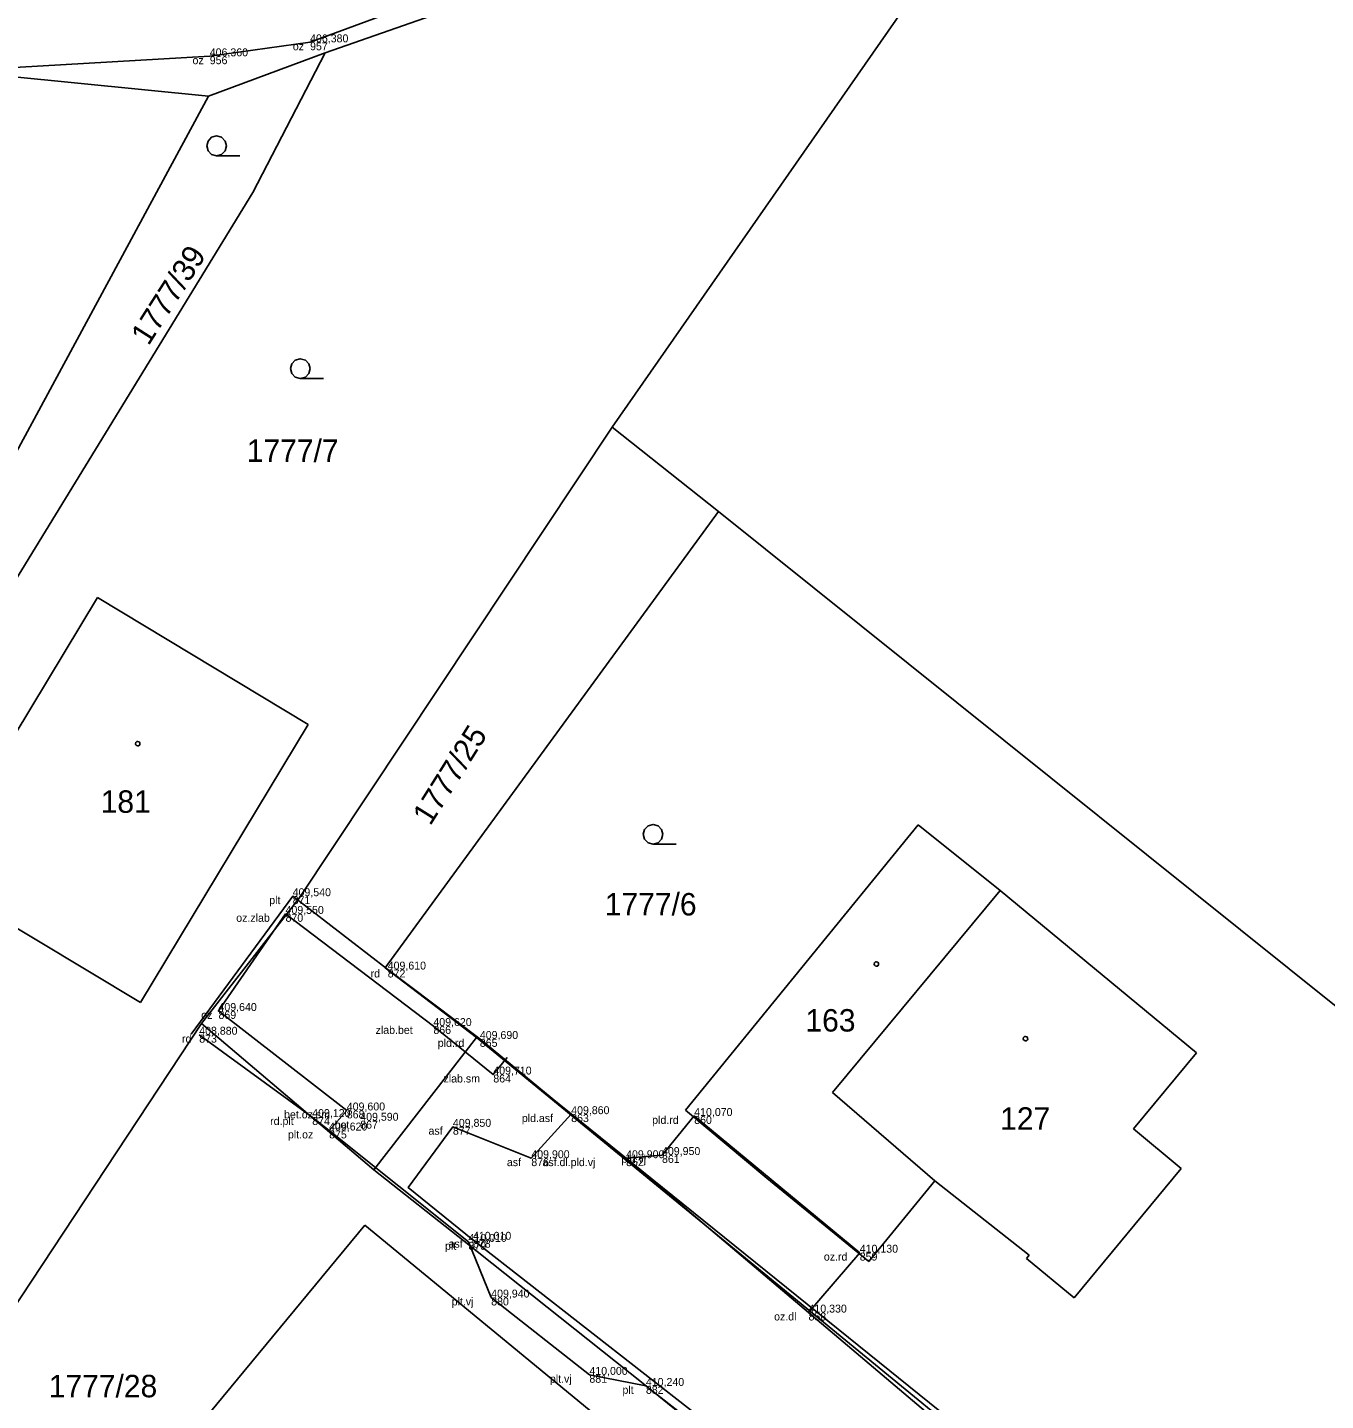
# Model space of a CAD drawing. Extents: x -747792 to -745414, y -1093712 to -1091463.
# Drawn here: x -746956.8 to -746907.6, y -1092211.1 to -1092159 of the extents above; entities that cross this region are included whole.
import ezdxf

# ---------------------------------------------------------------- set-up
doc = ezdxf.new("R2010")
doc.units = 0
for name, color, linetype in [('Budovy', 7, 'Continuous'), ('Hladina', 7, 'Continuous'), ('Koleje_dopravní prvky', 7, 'Continuous'), ('Nezařazené objekty', 7, 'Continuous'), ('Nivelační značky_hrany', 7, 'Continuous'), ('Ploty_opěrné zdi', 7, 'Continuous'), ('Popisy objektů_povrchů', 7, 'Continuous'), ('Pracovní_bod PPBP - výška', 7, 'Continuous'), ('Rozhraní ploch', 7, 'Continuous'), ('Stromy_porost', 7, 'Continuous'), ('Výškopis', 7, 'Continuous')]:
    doc.layers.add(name, color=color, linetype=linetype)

msp = doc.modelspace()

# ---------------------------------------------------------------- linework, layer by layer
at = {"layer": 'Budovy'}
for points in [[(-746949.6, -1092163.9), (-746949.79, -1092163.85), (-746949.925, -1092163.71), (-746949.975, -1092163.525), (-746949.925, -1092163.34), (-746949.79, -1092163.2), (-746949.6, -1092163.15), (-746949.41, -1092163.2), (-746949.275, -1092163.34), (-746949.225, -1092163.525), (-746949.275, -1092163.71), (-746949.41, -1092163.85), (-746949.6, -1092163.9), (-746948.725, -1092163.9)], [(-746946.43, -1092172.34), (-746946.62, -1092172.29), (-746946.755, -1092172.15), (-746946.805, -1092171.965), (-746946.755, -1092171.78), (-746946.62, -1092171.64), (-746946.43, -1092171.59), (-746946.24, -1092171.64), (-746946.105, -1092171.78), (-746946.055, -1092171.965), (-746946.105, -1092172.15), (-746946.24, -1092172.29), (-746946.43, -1092172.34), (-746945.555, -1092172.34)], [(-746933.07, -1092189.99), (-746933.26, -1092189.94), (-746933.395, -1092189.8), (-746933.445, -1092189.615), (-746933.395, -1092189.43), (-746933.26, -1092189.29), (-746933.07, -1092189.24), (-746932.88, -1092189.29), (-746932.745, -1092189.43), (-746932.695, -1092189.615), (-746932.745, -1092189.8), (-746932.88, -1092189.94), (-746933.07, -1092189.99), (-746932.195, -1092189.99)]]:
    msp.add_lwpolyline(points, dxfattribs=at)
at = {"layer": 'Hladina'}
for p, q in [((-746946.06, -1092159.6), (-746946.06, -1092159.6)), ((-746949.86, -1092160.13), (-746949.86, -1092160.13)), ((-746946.72, -1092191.96), (-746946.72, -1092191.96)), ((-746946.99, -1092192.63), (-746946.99, -1092192.63)), ((-746943.12, -1092194.74), (-746943.12, -1092194.74)), ((-746949.53, -1092196.31), (-746949.53, -1092196.31)), ((-746941.39, -1092196.88), (-746941.39, -1092196.88)), ((-746950.26, -1092197.21), (-746950.26, -1092197.21)), ((-746939.63, -1092197.37), (-746939.63, -1092197.37)), ((-746939.12, -1092198.72), (-746939.12, -1092198.72)), ((-746944.67, -1092200.08), (-746944.67, -1092200.08)), ((-746936.17, -1092200.22), (-746936.17, -1092200.22)), ((-746945.98, -1092200.33), (-746945.98, -1092200.33)), ((-746944.16, -1092200.47), (-746944.16, -1092200.47)), ((-746940.65, -1092200.7), (-746940.65, -1092200.7)), ((-746931.51, -1092200.29), (-746931.51, -1092200.29)), ((-746945.34, -1092200.84), (-746945.34, -1092200.84)), ((-746932.73, -1092201.77), (-746932.73, -1092201.77)), ((-746937.68, -1092201.89), (-746937.68, -1092201.89)), ((-746934.09, -1092201.89), (-746934.09, -1092201.89)), ((-746940.06, -1092205.06), (-746940.06, -1092205.06)), ((-746939.89, -1092204.98), (-746939.89, -1092204.98)), ((-746925.24, -1092205.47), (-746925.24, -1092205.47)), ((-746939.2, -1092207.17), (-746939.2, -1092207.17)), ((-746927.18, -1092207.74), (-746927.18, -1092207.74)), ((-746935.48, -1092210.1), (-746935.48, -1092210.1)), ((-746933.34, -1092210.52), (-746933.34, -1092210.52))]:
    msp.add_line(p, q, dxfattribs=at)
at = {"layer": 'Nezařazené objekty'}
for points in [[(-746898.2, -1092136.84), (-746901.82, -1092139.52), (-746907.92, -1092143.31), (-746914.89, -1092147.23), (-746921.83, -1092150.74), (-746928.99, -1092153.69), (-746935.25, -1092155.97), (-746941.16, -1092157.77), (-746946.06, -1092159.6), (-746949.86, -1092160.13)], [(-746949.86, -1092160.13), (-746970.11, -1092161.3), (-746974.56, -1092162.83), (-746976.66, -1092164.29), (-746978.34, -1092165.95)], [(-746950.56, -1092197.19), (-746946.72, -1092191.96), (-746943.12, -1092194.74)], [(-746945.34, -1092200.84), (-746944.67, -1092200.08), (-746949.53, -1092196.31), (-746946.99, -1092192.63)], [(-746939.63, -1092197.37), (-746936.17, -1092200.22)], [(-746936.17, -1092200.22), (-746934.09, -1092201.89)], [(-746945.34, -1092200.84), (-746945.98, -1092200.33)], [(-746932.73, -1092201.77), (-746931.51, -1092200.29)], [(-746939.2, -1092207.17), (-746940.06, -1092205.06), (-746945.34, -1092200.84)], [(-746925.24, -1092205.47), (-746927.18, -1092207.74), (-746922.75, -1092211.49)], [(-746930.18, -1092221.49), (-746926.79, -1092217.36), (-746927.43, -1092215.14), (-746933.34, -1092210.52), (-746935.48, -1092210.1)]]:
    msp.add_lwpolyline(points, dxfattribs=at)
at = {"layer": 'Nivelační značky_hrany'}
for points in [[(-746946.99, -1092192.63), (-746941.39, -1092196.88), (-746939.12, -1092198.72), (-746938.59, -1092198.07)], [(-746954.31, -1092247.58), (-746952.61, -1092247.87), (-746950.91, -1092247.12), (-746949.5, -1092246), (-746932.35, -1092225.35), (-746926.2, -1092217.84), (-746927.09, -1092214.99), (-746939.89, -1092204.98), (-746942.35, -1092203), (-746940.65, -1092200.7), (-746937.68, -1092201.89), (-746936.17, -1092200.22)], [(-746934.09, -1092201.89), (-746927.18, -1092207.74)]]:
    msp.add_lwpolyline(points, dxfattribs=at)
at = {"layer": 'Ploty_opěrné zdi'}
for points in [[(-746952.59, -1092186.095), (-746952.54, -1092186.105), (-746952.515, -1092186.15), (-746952.505, -1092186.18), (-746952.515, -1092186.225), (-746952.555, -1092186.26), (-746952.59, -1092186.265), (-746952.635, -1092186.25), (-746952.665, -1092186.22), (-746952.675, -1092186.18), (-746952.665, -1092186.135), (-746952.625, -1092186.1)], [(-746924.61, -1092194.445), (-746924.56, -1092194.455), (-746924.535, -1092194.5), (-746924.525, -1092194.53), (-746924.535, -1092194.575), (-746924.575, -1092194.61), (-746924.61, -1092194.615), (-746924.655, -1092194.6), (-746924.685, -1092194.57), (-746924.695, -1092194.53), (-746924.685, -1092194.485), (-746924.645, -1092194.45)], [(-746918.96, -1092197.275), (-746918.91, -1092197.285), (-746918.885, -1092197.33), (-746918.875, -1092197.36), (-746918.885, -1092197.405), (-746918.925, -1092197.44), (-746918.96, -1092197.445), (-746919.005, -1092197.43), (-746919.035, -1092197.4), (-746919.045, -1092197.36), (-746919.035, -1092197.315), (-746918.995, -1092197.28)]]:
    msp.add_lwpolyline(points, close=True, dxfattribs=at)
at = {"layer": 'Popisy objektů_povrchů'}
for points in [[(-746943.12, -1092194.74), (-746939.63, -1092197.37)], [(-746945.98, -1092200.33), (-746950.26, -1092197.21)], [(-746931.51, -1092200.29), (-746925.24, -1092205.47)]]:
    msp.add_lwpolyline(points, dxfattribs=at)
at = {"layer": 'Pracovní_bod PPBP - výška'}
for points in [[(-746934.09, -1092201.89), (-746932.73, -1092201.77)], [(-746939.2, -1092207.17), (-746935.48, -1092210.1)]]:
    msp.add_lwpolyline(points, dxfattribs=at)
at = {"layer": 'Stromy_porost'}
for points in [[(-746918.07, -1092150.41), (-746945.49, -1092160)], [(-746918.07, -1092150.41), (-746934.62, -1092174.19)], [(-746945.49, -1092160), (-746948.23, -1092165.29), (-746962.05, -1092187.86), (-746971.93, -1092204.37)], [(-746945.49, -1092160), (-746949.91, -1092161.64)], [(-746949.91, -1092161.64), (-746959.95, -1092160.64)], [(-746959.95, -1092180.22), (-746949.91, -1092161.64)], [(-746946.48, -1092192.03), (-746934.62, -1092174.19)], [(-746934.62, -1092174.19), (-746930.59, -1092177.38)], [(-746943.21, -1092194.67), (-746930.59, -1092177.38)], [(-746901.79, -1092200.47), (-746930.59, -1092177.38)], [(-746960.47, -1092191.19), (-746954.11, -1092180.64)], [(-746954.11, -1092180.64), (-746946.13, -1092185.45)], [(-746946.13, -1092185.45), (-746952.49, -1092195.99)], [(-746931.84, -1092200.07), (-746923.03, -1092189.26)], [(-746923.03, -1092189.26), (-746919.92, -1092191.74)], [(-746952.49, -1092195.99), (-746960.47, -1092191.19)], [(-746919.92, -1092191.74), (-746926.27, -1092199.4)], [(-746912.48, -1092197.9), (-746919.92, -1092191.74)], [(-746950.17, -1092196.79), (-746946.48, -1092192.03)], [(-746943.21, -1092194.67), (-746939.76, -1092197.31)], [(-746950.17, -1092196.79), (-746963.07, -1092216.32)], [(-746943.65, -1092202.33), (-746950.17, -1092196.79)], [(-746939.76, -1092197.31), (-746943.65, -1092202.33)], [(-746939.76, -1092197.31), (-746905.81, -1092225.18)], [(-746908.12, -1092222.84), (-746939.76, -1092197.31)], [(-746914.87, -1092200.78), (-746912.48, -1092197.9)], [(-746926.27, -1092199.4), (-746922.4, -1092202.75)], [(-746928.76, -1092202.65), (-746931.84, -1092200.07)], [(-746913.06, -1092202.28), (-746914.87, -1092200.78)], [(-746917.12, -1092207.18), (-746913.06, -1092202.28)], [(-746940.23, -1092205.04), (-746943.65, -1092202.33)], [(-746924.9, -1092205.81), (-746928.76, -1092202.65)], [(-746924.9, -1092205.81), (-746922.4, -1092202.75)], [(-746922.4, -1092202.75), (-746918.82, -1092205.57)], [(-746965.16, -1092230.04), (-746943.99, -1092204.43)], [(-746927.56, -1092217.96), (-746943.99, -1092204.43)], [(-746933.45, -1092210.43), (-746940.23, -1092205.04)], [(-746918.82, -1092205.57), (-746918.92, -1092205.69)], [(-746918.92, -1092205.69), (-746917.12, -1092207.18)], [(-746927.65, -1092215.11), (-746933.45, -1092210.43)]]:
    msp.add_lwpolyline(points, dxfattribs=at)

# ---------------------------------------------------------------- texts
at = {"layer": 'Koleje_dopravní prvky'}
for s, rotation, p in [('1777/39', 57.4677, (-746952.181, -1092171.128)), ('1777/25', 57.8687, (-746941.507, -1092189.32))]:
    msp.add_text(s, height=0.85, rotation=rotation, dxfattribs=at).set_placement(p)
for s, p in [('1777/7', (-746948.457, -1092175.5)), ('181', (-746953.992, -1092188.8)), ('1777/6', (-746934.897, -1092192.69)), ('163', (-746927.297, -1092197.09)), ('127', (-746919.92, -1092200.81)), ('1777/28', (-746955.958, -1092210.95))]:
    msp.add_text(s, height=0.85, dxfattribs=at).set_placement(p)
at = {"layer": 'Rozhraní ploch'}
for s, p in [('957', (-746946.06, -1092159.9)), ('956', (-746949.86, -1092160.43)), (' oz', (-746946.825, -1092159.9)), (' oz', (-746950.625, -1092160.43)), (' plt', (-746947.719, -1092192.26)), ('871', (-746946.72, -1092192.26)), (' oz.zlab', (-746948.969, -1092192.93)), ('870', (-746946.99, -1092192.93)), (' rd', (-746943.881, -1092195.04)), ('872', (-746943.12, -1092195.04)), (' oz', (-746950.295, -1092196.61)), ('869', (-746949.53, -1092196.61)), (' zlab.bet', (-746943.69, -1092197.18)), ('866', (-746941.39, -1092197.18)), (' rd', (-746951.021, -1092197.51)), ('873', (-746950.26, -1092197.51)), (' pld.rd', (-746941.335, -1092197.67)), ('865', (-746939.63, -1092197.67)), (' zlab.sm', (-746941.118, -1092199.02)), ('864', (-746939.12, -1092199.02)), (' bet.oz.sm', (-746947.157, -1092200.38)), ('868', (-746944.67, -1092200.38)), (' pld.asf', (-746938.151, -1092200.52)), ('863', (-746936.17, -1092200.52)), (' rd.plt', (-746947.685, -1092200.63)), ('874', (-746945.98, -1092200.63)), (' bet', (-746945.246, -1092200.77)), ('867', (-746944.16, -1092200.77)), (' asf', (-746941.687, -1092201)), ('877', (-746940.65, -1092201)), (' pld.rd', (-746933.215, -1092200.59)), ('860', (-746931.51, -1092200.59)), (' plt.oz', (-746947.01, -1092201.14)), ('875', (-746945.34, -1092201.14)), (' pld.vj', (-746934.379, -1092202.07)), ('861', (-746932.73, -1092202.07)), (' asf', (-746938.717, -1092202.19)), ('876', (-746937.68, -1092202.19)), (' asf.dl.pld.vj', (-746937.37, -1092202.19)), ('862', (-746934.09, -1092202.19)), (' plt', (-746941.059, -1092205.36)), (' asf', (-746940.927, -1092205.28)), ('879', (-746940.06, -1092205.36)), ('878', (-746939.89, -1092205.28)), (' oz.rd', (-746926.711, -1092205.77)), ('859', (-746925.24, -1092205.77)), (' plt.vj', (-746940.808, -1092207.47)), ('880', (-746939.2, -1092207.47)), (' oz.dl', (-746928.595, -1092208.04)), ('858', (-746927.18, -1092208.04)), (' plt.vj', (-746937.088, -1092210.4)), ('881', (-746935.48, -1092210.4)), (' plt', (-746934.339, -1092210.82)), ('882', (-746933.34, -1092210.82))]:
    msp.add_text(s, height=0.3, dxfattribs=at).set_placement(p)
at = {"layer": 'Výškopis'}
for s, p in [('406,380', (-746946.06, -1092159.6)), ('406,360', (-746949.86, -1092160.13)), ('409,540', (-746946.72, -1092191.96)), ('409,550', (-746946.99, -1092192.63)), ('409,610', (-746943.12, -1092194.74)), ('409,640', (-746949.53, -1092196.31)), ('409,620', (-746941.39, -1092196.88)), ('408,880', (-746950.26, -1092197.21)), ('409,690', (-746939.63, -1092197.37)), ('409,710', (-746939.12, -1092198.72)), ('409,120', (-746945.98, -1092200.33)), ('409,600', (-746944.67, -1092200.08)), ('409,590', (-746944.16, -1092200.47)), ('409,860', (-746936.17, -1092200.22)), ('410,070', (-746931.51, -1092200.29)), ('409,620', (-746945.34, -1092200.84)), ('409,850', (-746940.65, -1092200.7)), ('409,900', (-746937.68, -1092201.89)), ('409,900', (-746934.09, -1092201.89)), ('409,950', (-746932.73, -1092201.77)), ('410,010', (-746940.06, -1092205.06)), ('410,010', (-746939.89, -1092204.98)), ('410,130', (-746925.24, -1092205.47)), ('409,940', (-746939.2, -1092207.17)), ('410,330', (-746927.18, -1092207.74)), ('410,000', (-746935.48, -1092210.1)), ('410,240', (-746933.34, -1092210.52))]:
    msp.add_text(s, height=0.3, dxfattribs=at).set_placement(p)

doc.saveas('drawing.dxf')
